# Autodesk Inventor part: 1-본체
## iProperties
Created: 2015-01
Part Number: 1-본체
Document SubType Name: Modeling
Designer: lee
Density: 2.71 g/cm^3
Material: 알루미늄-6061
Mass: 1021.34 g
Surface Area: 1059.8 cm^2
Volume: 376.878 cm^3
Author: lee
